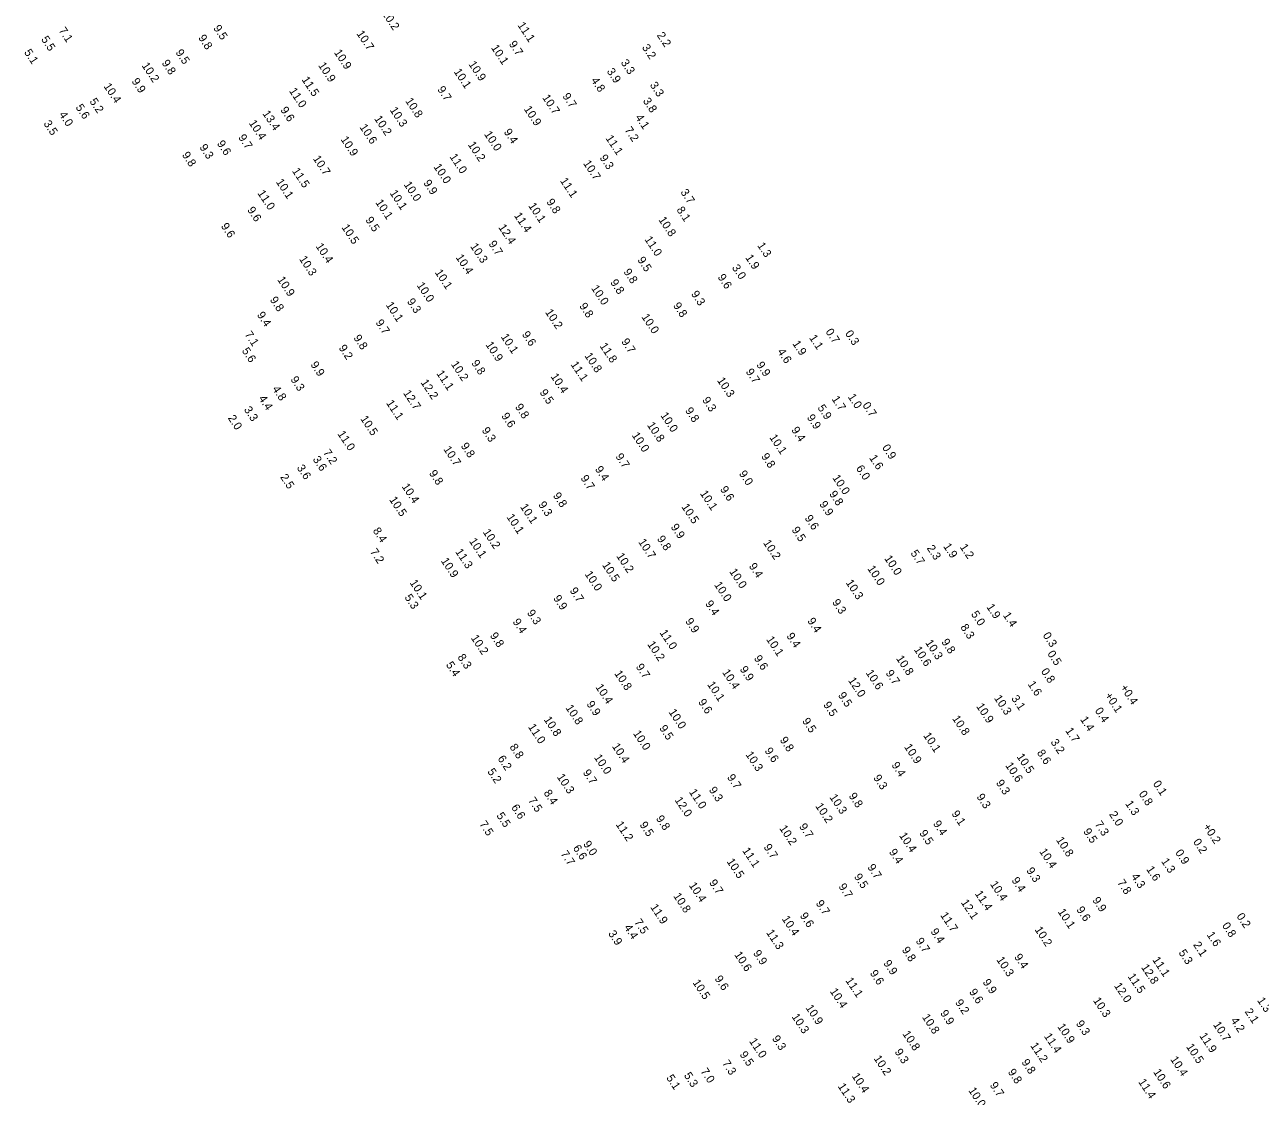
# Model space of a CAD drawing. Extents: x 815385 to 820851, y 582449 to 604245.
# Drawn here: x 816786 to 817540, y 596348 to 597003 of the extents above; entities that cross this region are included whole.
import ezdxf

# ---------------------------------------------------------------- set-up
doc = ezdxf.new("R2010")
doc.units = 0
doc.layers.add('V-TOPO-SOUN-020509C', color=7, linetype='Continuous')

msp = doc.modelspace()

# ---------------------------------------------------------------- texts
at = {"layer": 'V-TOPO-SOUN-020509C'}
for s, p in [('10.2 ', (817003.68, 597009.85)), ('7.1', (816806.25, 596999.34)), ('9.5', (816900.73, 597000.8)), ('10.7 ', (816988.17, 596997.43)), ('11.1 ', (817086.53, 597002.57)), ('2.2', (817171.64, 596996.43)), ('5.5', (816795.54, 596993.99)), ('9.8', (816891.52, 596994.87)), ('9.7', (817081.23, 596991.09)), ('3.2', (817162.51, 596989.01)), ('5.1', (816785.13, 596986)), ('9.5', (816877.64, 596985.9)), ('10.9 ', (816974.45, 596985.87)), ('10.1 ', (817070.4, 596988.78)), ('10.2 ', (816856.98, 596977.94)), ('9.8', (816869.19, 596979.5)), ('10.9 ', (816964.77, 596978.05)), ('10.1 ', (817047.6, 596974.18)), ('10.9 ', (817056.61, 596978.75)), ('3.9', (817141.04, 596974.38)), ('3.3', (817149.59, 596979.75)), ('9.9', (816850.79, 596968.31)), ('11.5 ', (816954.68, 596969.34)), ('4.8', (817131.44, 596968.89)), ('10.4 ', (816833.71, 596965.28)), ('11.0 ', (816947, 596962.43)), ('9.7', (817037.54, 596963.39)), ('9.7', (817113.96, 596959.22)), ('3.3', (817167.32, 596966.04)), ('5.6', (816816.59, 596952.43)), ('5.2', (816825.08, 596956.04)), ('10.8 ', (817017.95, 596956.32)), ('10.9 ', (817090.41, 596951.36)), ('10.7 ', (817101.64, 596958.33)), ('3.8', (817163.08, 596956.33)), ('4.0', (816806.45, 596947.92)), ('13.4 ', (816930.74, 596948.58)), ('9.6', (816941.67, 596950.83)), ('10.2 ', (816999, 596945.46)), ('10.3 ', (817008.54, 596950.73)), ('4.1', (817158.45, 596946.28)), ('3.5', (816797, 596942.51)), ('10.4 ', (816922.38, 596942.79)), ('10.6 ', (816990.05, 596940.28)), ('9.4', (817078.13, 596937.38)), ('7.2', (817151.97, 596938.6)), ('9.6', (816902.93, 596930.25)), ('9.7', (816915.95, 596934.01)), ('10.9 ', (816978.48, 596932.85)), ('10.2 ', (817056.22, 596929.61)), ('10.0 ', (817066.15, 596936.01)), ('11.1 ', (817140.31, 596933.54)), ('9.8', (816881.56, 596923.32)), ('9.3', (816892.25, 596928)), ('11.0 ', (817045.02, 596922.22)), ('9.3', (817136.66, 596921.62)), ('10.7 ', (816961.55, 596921.1)), ('10.0 ', (817035.24, 596916.07)), ('10.7 ', (817126.6, 596918.19)), ('10.1 ', (816938.98, 596906.85)), ('11.5 ', (816948.81, 596913.53)), ('9.9', (817029.03, 596906.23)), ('11.1 ', (817112.52, 596907.52)), ('11.0 ', (816927.69, 596899.97)), ('10.1 ', (817008.47, 596900.05)), ('10.0 ', (817017.04, 596905.25)), ('3.7', (817186.06, 596900.62)), ('10.1 ', (816999.71, 596894.3)), ('10.1 ', (817093.14, 596892.25)), ('9.8', (817104.17, 596894.66)), ('9.6', (816921.42, 596889.74)), ('9.5', (816993.62, 596883.61)), ('11.4 ', (817084.42, 596886.29)), ('10.8 ', (817172.62, 596883.74)), ('8.1', (817183.65, 596889.82)), ('9.6', (816905.35, 596879.85)), ('10.5 ', (816979.04, 596879.12)), ('12.4 ', (817074.84, 596879.1)), ('9.7', (817068.82, 596869.06)), ('11.0 ', (817164.1, 596871.79)), ('10.4 ', (816963.23, 596867.56)), ('10.4 ', (817048.78, 596860.74)), ('10.3 ', (817057.63, 596867.53)), ('1.3', (817232.98, 596868.02)), ('10.3 ', (816953.15, 596859.77)), ('9.5', (817159.77, 596859.21)), ('3.0', (817217.48, 596854.47)), ('1.9', (817225.69, 596860.61)), ('10.9 ', (816939.78, 596847.17)), ('10.1 ', (817036.03, 596851.55)), ('9.8', (817143.15, 596845.46)), ('9.8', (817151.23, 596851.94)), ('9.6', (817208.78, 596848.67)), ('10.0 ', (817024.95, 596843.7)), ('10.0 ', (817131.53, 596841.93)), ('9.3', (817192.53, 596838.45)), ('9.8', (816935.25, 596834.87)), ('10.1 ', (817006.08, 596831.69)), ('9.3', (817019.02, 596833.83)), ('9.8', (817124.25, 596831.05)), ('9.8', (817181.56, 596831.33)), ('9.4', (816927.37, 596825.63)), ('10.2 ', (817103.4, 596827.27)), ('10.0 ', (817162.27, 596824.41)), ('9.7', (816999.82, 596820.91)), ('0.7', (817274.66, 596815.32)), ('7.1', (816919.86, 596813.72)), ('9.8', (816986.31, 596811.59)), ('10.1 ', (817076.36, 596812.26)), ('9.6', (817089.21, 596813.74)), ('9.7', (817149.91, 596809.31)), ('1.9', (817254.45, 596808.06)), ('1.1', (817264.68, 596811.62)), ('0.3', (817286.61, 596814.28)), ('5.6', (816918.12, 596803.72)), ('9.2', (816977.3, 596805.48)), ('10.9 ', (817066.99, 596807.44)), ('10.8 ', (817127.44, 596800.66)), ('11.8 ', (817136.7, 596806.64)), ('4.6', (817245.27, 596803.14)), ('9.9', (816960.09, 596795.27)), ('10.2 ', (817045.88, 596795.51)), ('9.8', (817058.33, 596796.21)), ('11.1 ', (817118.98, 596795.32)), ('9.9', (817232.42, 596795.16)), ('9.3', (816947.85, 596786.23)), ('11.1 ', (817036.95, 596789.87)), ('10.4 ', (817106.77, 596788.03)), ('10.3 ', (817208.44, 596785.6)), ('9.7', (817225.91, 596790.91)), ('4.8', (816936.72, 596780.39)), ('12.7 ', (817016.71, 596777.86)), ('12.2 ', (817027.38, 596784.35)), ('9.5', (817100.01, 596778.29)), ('4.4', (816928.35, 596774.57)), ('11.1 ', (817006.28, 596771.78)), ('9.3', (817199.32, 596773.62)), ('1.7', (817278.42, 596774.23)), ('1.0', (817288.3, 596775.54)), ('0.7', (817297.23, 596770.43)), ('2.0', (816909.62, 596762.59)), ('3.3', (816919.41, 596767.79)), ('9.6', (817076.63, 596763.92)), ('9.8', (817085, 596769.43)), ('10.0 ', (817173.82, 596764.26)), ('9.8', (817188.89, 596767.21)), ('9.9', (817263.25, 596762.98)), ('5.9', (817269.76, 596768.89)), ('10.5 ', (816990.53, 596762.18)), ('9.3', (817064.69, 596755.12)), ('10.8 ', (817165.67, 596758.29)), ('9.4', (817253.77, 596755.34)), ('11.0 ', (816976.59, 596752.94)), ('10.0 ', (817156.34, 596752.09)), ('10.1 ', (817240.37, 596750.78)), ('7.2', (816967.78, 596741.54)), ('10.7 ', (817041.26, 596743.61)), ('9.8', (817051.86, 596745.63)), ('0.9', (817309.22, 596744.59)), ('3.6', (816951.7, 596732.23)), ('3.6', (816961.44, 596737.4)), ('9.7', (817146.34, 596739.14)), ('9.8', (817235.36, 596739.23)), ('1.6', (817301.34, 596738.27)), ('2.5', (816941.55, 596726.52)), ('9.8', (817032.49, 596728.92)), ('9.7', (817125.01, 596725.88)), ('9.4', (817133.84, 596731.37)), ('9.0', (817221.76, 596728.65)), ('10.0 ', (817278.86, 596726.12)), ('6.0', (817293.28, 596731.91)), ('10.4 ', (817015.82, 596720.8)), ('9.6', (817210.25, 596719.11)), ('10.5 ', (817008.18, 596712.78)), ('9.3', (817099.21, 596709.76)), ('9.8', (817108.17, 596715.24)), ('10.1 ', (817198, 596716.54)), ('9.9', (817270.88, 596710.02)), ('9.8', (817276.88, 596716.25)), ('10.1 ', (817088.13, 596708.37)), ('10.5 ', (817186.68, 596708.39)), ('10.1 ', (817079.83, 596702.14)), ('9.9', (817180.12, 596696.1)), ('9.6', (817261.94, 596701.48)), ('8.4', (816998.12, 596693.8)), ('10.1 ', (817056.96, 596687.43)), ('10.2 ', (817065.35, 596692.97)), ('9.8', (817171.73, 596688.89)), ('9.5', (817253.96, 596694.33)), ('7.2', (816996.43, 596680.92)), ('11.3 ', (817048.5, 596680.94)), ('10.7 ', (817160.27, 596686.94)), ('10.2 ', (817236.57, 596686.38)), ('5.7', (817326.57, 596680.12)), ('2.3', (817336.51, 596683.15)), ('1.9', (817346.59, 596684.24)), ('1.2', (817356.69, 596683.83)), ('10.9 ', (817039.75, 596675.4)), ('10.5 ', (817138.21, 596672.87)), ('10.2 ', (817146.87, 596678.33)), ('9.4', (817227.82, 596672.16)), ('10.0 ', (817310.56, 596676.88)), ('10.0 ', (817127.56, 596667.29)), ('10.0 ', (817215.88, 596668.82)), ('10.0 ', (817300.24, 596670.66)), ('10.1 ', (817020.67, 596662.02)), ('9.7', (817118.39, 596657.23)), ('10.0 ', (817206.63, 596660.79)), ('10.3 ', (817287, 596662.07)), ('5.3', (817017.49, 596653.1)), ('9.9', (817108.34, 596652.55)), ('9.4', (817201.16, 596649.25)), ('9.3', (817278.69, 596650.1)), ('9.3', (817092.29, 596643.65)), ('5.0', (817363.52, 596642.89)), ('1.9', (817372.97, 596647.22)), ('1.4', (817383.01, 596642.18)), ('9.4', (817083.54, 596638.21)), ('9.9', (817188.97, 596638.5)), ('9.4', (817263.55, 596638.7)), ('8.3', (817357.05, 596634.86)), ('10.2 ', (817058.05, 596628.31)), ('9.8', (817069.66, 596629.75)), ('11.0 ', (817173.33, 596631.5)), ('10.1 ', (817238.42, 596627.46)), ('9.4', (817250.79, 596629.51)), ('0.3', (817407.35, 596629.86)), ('10.2 ', (817165.82, 596624.45)), ('10.6 ', (817328.63, 596621.22)), ('10.3 ', (817335.6, 596625.36)), ('9.8', (817345.4, 596625.87)), ('5.4', (817042.79, 596611.91)), ('8.3', (817049.86, 596616.56)), ('9.6', (817230.92, 596615.85)), ('10.8 ', (817317.78, 596615.74)), ('0.5', (817410.16, 596618.67)), ('10.8 ', (817145.68, 596606.61)), ('9.7', (817158.78, 596610.68)), ('10.4 ', (817211.55, 596607.3)), ('9.9', (817222.28, 596609.19)), ('10.6 ', (817299.24, 596606.99)), ('9.7', (817311.4, 596606.84)), ('0.8', (817406.25, 596607.89)), ('10.4 ', (817134.12, 596598.3)), ('10.1 ', (817202.42, 596599.86)), ('12.0 ', (817288.47, 596602.37)), ('1.6', (817398.18, 596600.06)), ('+0.4 ', (817454.67, 596597.95)), ('9.6', (817196.86, 596589.15)), ('9.5', (817282.29, 596593.3)), ('10.3 ', (817377.61, 596591.55)), ('3.1', (817388.1, 596591.38)), ('+0.1 ', (817445.22, 596593.08)), ('10.8 ', (817115.86, 596585.62)), ('9.9', (817128.66, 596587.92)), ('10.0 ', (817178.83, 596583.02)), ('9.5', (817273.26, 596587.5)), ('10.9 ', (817366.7, 596586.55)), ('0.4', (817439.17, 596583.88)), ('11.0 ', (817092.96, 596573.96)), ('10.8 ', (817102.57, 596578.47)), ('9.5', (817260.38, 596577.56)), ('10.8 ', (817352.04, 596579.08)), ('1.4', (817430.22, 596578.52)), ('10.0 ', (817157.1, 596569.99)), ('9.5', (817173.11, 596573.19)), ('10.1 ', (817334.37, 596568.71)), ('1.7', (817421.16, 596571.66)), ('8.8', (817081.66, 596561.7)), ('10.4 ', (817144.24, 596562.12)), ('9.6', (817237.47, 596559.42)), ('9.8', (817246.72, 596566)), ('10.9 ', (817322.68, 596561.73)), ('3.2', (817412.11, 596564.69)), ('6.2', (817074.35, 596554.61)), ('10.0 ', (817133.27, 596555.33)), ('10.3 ', (817225.8, 596557.1)), ('10.5 ', (817391.38, 596555.81)), ('8.6', (817403.8, 596558.18)), ('5.2', (817068.11, 596546.7)), ('9.7', (817126.43, 596546.05)), ('9.4', (817314.96, 596550.68)), ('10.6 ', (817384.48, 596550.44)), ('10.3 ', (817110.57, 596543.41)), ('9.7', (817214.52, 596543.17)), ('9.3', (817303.86, 596542.89)), ('9.3', (817378.76, 596539.75)), ('0.1', (817474.63, 596539.27)), ('7.5', (817093.03, 596529.08)), ('8.4', (817102.48, 596533.64)), ('12.0 ', (817182.51, 596529.31)), ('11.0 ', (817191.28, 596534.19)), ('9.3', (817203.4, 596535.48)), ('10.3 ', (817277.1, 596531.02)), ('9.8', (817288.84, 596531.83)), ('9.3', (817366.91, 596531.26)), ('0.8', (817465.96, 596533.06)), ('6.6', (817082.66, 596524.77)), ('10.2 ', (817268.43, 596525.58)), ('9.1', (817351.61, 596520.97)), ('1.3', (817457.71, 596527.08)), ('7.5', (817063.19, 596514.64)), ('5.5', (817073.64, 596519.83)), ('11.2 ', (817146.5, 596514.42)), ('9.5', (817161.08, 596514.19)), ('9.8', (817171.08, 596518.03)), ('9.4', (817340.31, 596514.86)), ('7.3', (817439.1, 596514.59)), ('2.0', (817447.9, 596520.57)), ('10.2 ', (817246.46, 596512.02)), ('9.7', (817258.51, 596513.14)), ('10.4 ', (817319.63, 596507.63)), ('9.5', (817331.94, 596509.1)), ('9.5', (817432.09, 596510.12)), ('+0.2 ', (817505.26, 596512.98)), ('6.6', (817120.35, 596499.94)), ('9.0', (817126.6, 596502.46)), ('9.7', (817236.84, 596500.55)), ('10.8 ', (817415.46, 596504.92)), ('0.2', (817499.14, 596503.74)), ('7.7', (817112.86, 596496.46)), ('10.5 ', (817214.32, 596491.73)), ('11.1 ', (817223.82, 596498.4)), ('9.4', (817313.42, 596497.56)), ('10.4 ', (817405.24, 596497.88)), ('1.3', (817479.69, 596491.87)), ('0.9', (817488.28, 596497.18)), ('9.7', (817300.25, 596488.27)), ('9.3', (817397.32, 596486.24)), ('1.6', (817470.57, 596487.04)), ('10.4 ', (817191.2, 596477.2)), ('9.7', (817203.55, 596478.84)), ('9.7', (817282.58, 596476.46)), ('9.5', (817292.07, 596482.46)), ('10.4 ', (817375.18, 596477.93)), ('9.4', (817388.28, 596480.28)), ('7.8', (817452.86, 596478.86)), ('4.3', (817461.35, 596482.58)), ('10.8 ', (817181.69, 596470.69)), ('11.4 ', (817365.88, 596472.09)), ('9.9', (817437.67, 596468.15)), ('11.9 ', (817167.64, 596463.86)), ('9.7', (817268.7, 596466.22)), ('12.1 ', (817357.38, 596466.71)), ('10.1 ', (817416.51, 596461.04)), ('9.6', (817427.9, 596462.36)), ('7.5', (817157.83, 596454.7)), ('10.4 ', (817247.98, 596456.7)), ('9.6', (817258.96, 596458.67)), ('11.7 ', (817344.76, 596458.95)), ('0.2', (817525.71, 596458.33)), ('3.9', (817141.92, 596447.74)), ('4.4', (817151.58, 596451.48)), ('11.3 ', (817238.43, 596448.31)), ('9.4', (817338.79, 596448.97)), ('10.2 ', (817402.39, 596450.15)), ('1.6', (817507.52, 596446.98)), ('0.8', (817516.84, 596452.63)), ('9.7', (817329.73, 596443.21)), ('2.1', (817499.2, 596440.9)), ('10.6 ', (817218.93, 596434.86)), ('9.9', (817230.42, 596435.76)), ('9.8', (817321.26, 596437.75)), ('10.3 ', (817379.04, 596431.75)), ('9.4', (817389.9, 596433.45)), ('11.1 ', (817474.3, 596431.7)), ('5.3', (817490.34, 596436.07)), ('9.6', (817301.72, 596423.57)), ('9.9', (817310, 596429.67)), ('12.8 ', (817467.44, 596427.13)), ('10.5 ', (817193.45, 596417.8)), ('9.6', (817206.92, 596420.19)), ('11.1 ', (817286.86, 596419.03)), ('9.9', (817370.65, 596418.08)), ('12.0 ', (817450.9, 596415.84)), ('11.5 ', (817459.26, 596421.53)), ('10.4 ', (817277.34, 596412.48)), ('9.6', (817362.36, 596412.1)), ('10.9 ', (817262.5, 596402.38)), ('9.2', (817353.82, 596405.63)), ('10.3 ', (817438.08, 596406.88)), ('2.1', (817530.72, 596400.1)), ('1.3', (817538.32, 596406.9)), ('10.3 ', (817253.97, 596396.97)), ('10.8 ', (817333.6, 596396.73)), ('9.9', (817344.69, 596399.13)), ('9.3', (817427.61, 596392.75)), ('4.2', (817522.12, 596394.61)), ('10.8 ', (817321.69, 596386.48)), ('10.9 ', (817416.28, 596390.91)), ('10.7 ', (817511.41, 596392.12)), ('11.0 ', (817228.03, 596381.99)), ('9.3', (817241.97, 596383.62)), ('11.2 ', (817399.76, 596379.28)), ('11.4 ', (817408.12, 596385.03)), ('10.5 ', (817494.96, 596378.62)), ('11.9 ', (817503, 596385.26)), ('9.5', (817222.2, 596373.93)), ('10.2 ', (817304.09, 596371.47)), ('9.3', (817316.88, 596375.47)), ('10.4 ', (817485.26, 596370.92)), ('7.0', (817198.34, 596363.61)), ('7.3', (817211.51, 596368.52)), ('9.8', (817386.04, 596363.19)), ('9.8', (817394.36, 596369.15)), ('10.6 ', (817474.83, 596363.17)), ('5.1', (817177.37, 596359.62)), ('5.3', (817188.16, 596361.08)), ('10.4 ', (817290.7, 596360.69)), ('9.7', (817374.99, 596355.16)), ('11.4 ', (817465.71, 596357.14)), ('11.3 ', (817282.15, 596354.46)), ('10.0 ', (817361.91, 596351.93))]:
    msp.add_text(s, height=5, rotation=303.614, dxfattribs=at).set_placement(p)

doc.saveas('drawing.dxf')
